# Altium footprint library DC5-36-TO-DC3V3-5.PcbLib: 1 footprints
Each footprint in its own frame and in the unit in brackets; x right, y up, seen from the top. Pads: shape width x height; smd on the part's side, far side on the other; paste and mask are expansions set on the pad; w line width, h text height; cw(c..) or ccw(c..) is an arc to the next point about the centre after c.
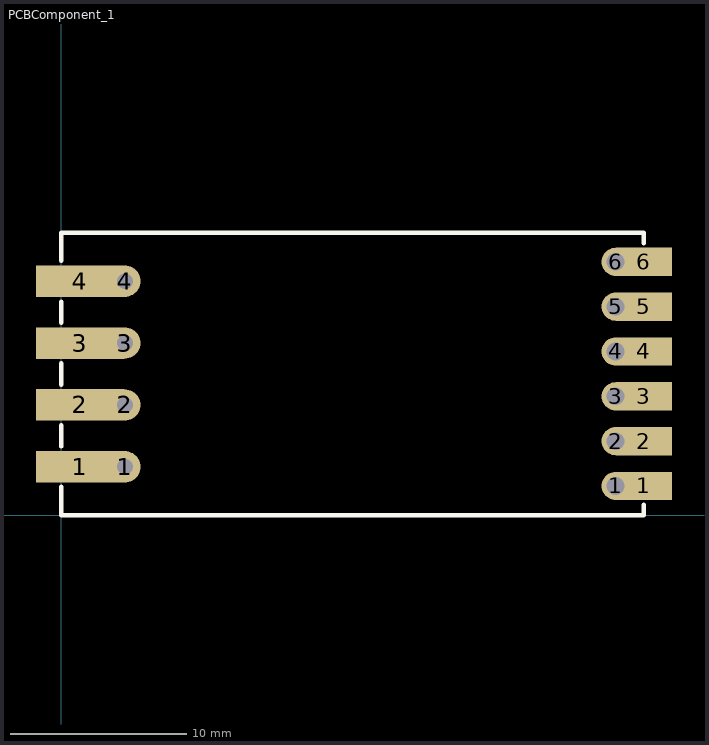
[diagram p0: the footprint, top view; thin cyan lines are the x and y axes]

## PCBComponent_1 [mm]
pads (20):
  rect 5x1.778 all layers, no hole: 1(1.05,2.742) 2(1.05,6.247) 3(1.05,9.752) 4(1.05,13.258)
  round 1.778 hole 0.889: 1(3.6,2.742) 2(3.6,6.247) 3(3.6,9.752) 4(3.6,13.258)
  round 1.6 hole 1: 1(31.395,1.655) 2(31.395,4.195) 3(31.395,6.735) 4(31.395,9.275) 5(31.395,11.815) 6(31.395,14.355)
  rect 3.2x1.6 all layers, no hole: 1(33.005,1.655) 2(33.005,4.195) 3(33.005,6.735) 4(33.005,9.275) 5(33.005,11.815) 6(33.005,14.355)
Top Overlay:
  lines w0.254: 0,1.603 0,0 1.2,0 31.8,0 33.005,0 33.005,0.603 ; 0,3.893 0,5.093 ; 0,7.398 0,8.598 ; 0,10.903 0,12.103 ; 0,14.403 0,16 1.2,16 31.8,16 33.005,16 33.005,15.403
